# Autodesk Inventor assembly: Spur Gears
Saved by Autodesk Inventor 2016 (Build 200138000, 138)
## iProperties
Created: 2015-03
Part Number: Spur Gears
Document SubType Name: Assembly
Designer: Uglješa
Categories: <?xml version="1.0" encoding="UTF-16"?> <MemberInstance><Categories><FamilyTemplate/><ParamToTemplateMap><ParamToTemplate><ParamToTemplate CategoryParameter="//
Mass: 1547.82 g
Surface Area: 438.622 cm^2
Volume: 197.174 cm^3
Density: 7.85 g/cm^3
ClientObjectVersion: 1
Author: Uglješa
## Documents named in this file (2)
- C:\Users\Ugljesa\Desktop\Turbokompr\Assembly1\Design Accelerator\Spur Gears1.iam
- C:\Users\Ugljesa\Desktop\Turbokompr\Assembly1\Design Accelerator\Spur Gear21.ipt
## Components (1 placed, 1 different names)
1. Spur Gear2:1
